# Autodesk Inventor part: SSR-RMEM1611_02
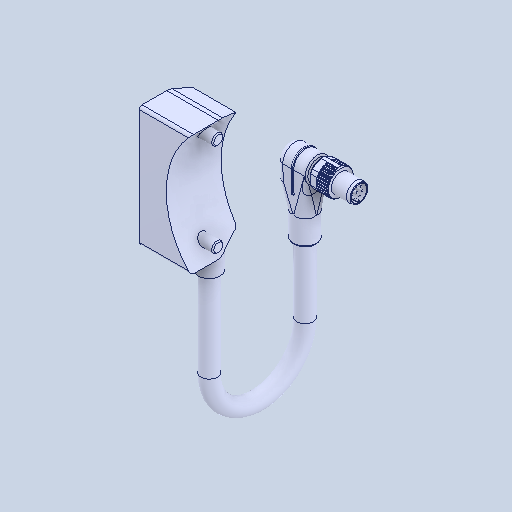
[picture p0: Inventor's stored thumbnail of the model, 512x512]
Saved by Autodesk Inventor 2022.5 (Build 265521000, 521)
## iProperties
Created: 2024-09
Part Number: SSR-RMEM1611_02
Material: 一般
Document SubType Name: Modeling
Designer: ImaoCorp
Density: 1 g/cm^3
Appearance: 既定
Author: ImaoCorp
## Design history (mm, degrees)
feature "SSR-RMEM1611_02"
node "ソリッド1"
